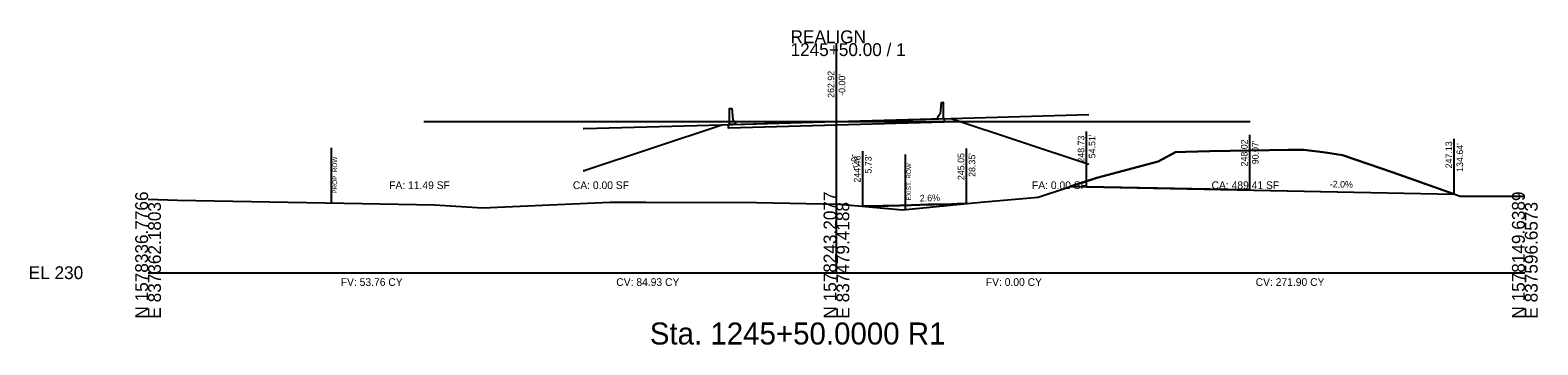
# Model space of a CAD drawing. Extents: x -26 to 6303, y -16 to 9563.
# Drawn here: x 1974.3 to 2302.8, y 6984.3 to 7052.8 of the extents above; entities that cross this region are included whole.
import ezdxf

# ---------------------------------------------------------------- set-up
doc = ezdxf.new("R2010")
doc.units = 0
for name, color, linetype in [('CONST_LV3', 7, 'Continuous'), ('Draft_XS_Grid', 7, 'Continuous'), ('Draft_XS_Text', 7, 'Continuous'), ('DTM_P_FINISHED_GRADE2', 7, 'Continuous'), ('DTM_TEMP_DROP', 7, 'Continuous'), ('DTM_X_GROUND', 7, 'Continuous'), ('TRANS_EOP_PAVED', 7, 'Continuous'), ('XS_CELL', 7, 'Continuous'), ('XS_M_SHAPES_EARTHWORK', 7, 'Continuous'), ('XS_P_ASPHALT', 7, 'Continuous'), ('XS_P_CONCRETE', 7, 'Continuous'), ('XS_P_GROUND', 7, 'Continuous'), ('XS_P_ROW', 7, 'Continuous'), ('XS_P_TX_CLEARZONE', 7, 'Continuous'), ('XS_P_TX_FS_BS', 7, 'Continuous'), ('XS_SHEET_EW_TX_AREA', 7, 'Continuous'), ('XS_SHEET_EW_TX_VOLUME', 7, 'Continuous'), ('XS_X_ROW', 7, 'Continuous')]:
    doc.layers.add(name, color=color, linetype=linetype)

msp = doc.modelspace()

# ---------------------------------------------------------------- linework, layer by layer
at = {"layer": 'CONST_LV3'}
for points in [[(2094.83, 7031.4), (2094.89, 7031.4), (2094.93, 7031.39), (2094.99, 7031.38), (2094.99, 7031.38), (2095, 7031.38), (2095, 7031.38), (2095, 7031.38), (2095, 7031.38), (2095.05, 7031.38), (2125, 7032.22), (2149.96, 7032.92), (2150, 7032.92), (2150, 7032.92), (2175, 7033.62), (2175, 7033.62), (2205, 7034.46)], [(2060.06, 7032.92), (2150.01, 7032.92), (2240.06, 7032.92), (2240.06, 7032.92), (2240.06, 7032.92)], [(2094.83, 7022.24), (2094.89, 7022.24), (2094.93, 7022.23), (2094.99, 7022.22), (2094.99, 7022.22), (2095, 7022.22), (2095, 7022.22), (2095, 7022.22), (2095, 7022.22), (2095.05, 7022.23), (2125, 7032.22), (2149.96, 7032.92), (2150, 7032.92), (2150, 7032.92), (2175, 7033.62), (2175, 7033.62), (2205, 7023.62)]]:
    msp.add_lwpolyline(points, dxfattribs=at)
at = {"layer": 'DTM_P_FINISHED_GRADE2'}
msp.add_lwpolyline([(2155.73, 7014.46), (2156.31, 7014.47), (2156.32, 7014.48), (2156.33, 7014.48), (2160.11, 7014.57), (2160.28, 7014.58), (2161.53, 7014.61), (2166.31, 7014.73), (2169.91, 7014.83), (2170.06, 7014.83), (2171.26, 7014.86), (2171.31, 7014.86), (2175, 7014.96), (2175.06, 7014.96), (2176.29, 7014.99), (2176.31, 7014.99), (2178.35, 7015.05)], dxfattribs=at)
at = {"layer": 'DTM_X_GROUND'}
msp.add_lwpolyline([(2000, 7016), (2006.4, 7015.79), (2046.66, 7015.1), (2062.44, 7014.77), (2072.86, 7014.16), (2100.71, 7015.34), (2108.48, 7015.37), (2132.61, 7015.33), (2150.67, 7014.92), (2164.43, 7013.67), (2181.43, 7015.35), (2193.97, 7016.46), (2206.72, 7020.66), (2220.1, 7024.25), (2223.85, 7026.23), (2226.12, 7026.34), (2231.37, 7026.5), (2240.19, 7026.61), (2248.41, 7026.74), (2251.87, 7026.8), (2256.54, 7026.18), (2260.3, 7025.61), (2271.31, 7021.81), (2285.94, 7016.67), (2300, 7016.69)], dxfattribs=at)
at = {"layer": 'XS_CELL'}
for p, q in [((2150, 7000), (2150, 7050)), ((2000, 7000), (2150, 7000)), ((2150, 7000), (2300, 7000))]:
    msp.add_line(p, q, dxfattribs=at)
at = {"layer": 'XS_M_SHAPES_EARTHWORK'}
msp.add_lwpolyline([(2155.73, 7014.46), (2164.43, 7013.67), (2178.35, 7015.05), (2176.31, 7014.99), (2175.06, 7014.96), (2171.31, 7014.86), (2170.06, 7014.83), (2166.31, 7014.73), (2161.31, 7014.6), (2160.06, 7014.57), (2156.31, 7014.47)], close=True, dxfattribs=at)
at = {"layer": 'XS_P_CONCRETE'}
for points in [[(2126.67, 7032.26), (2126.67, 7035.76), (2127.17, 7035.8), (2127.42, 7033.38), (2128, 7032.55), (2128, 7032.3), (2126.67, 7032.26)], [(2173.33, 7033.57), (2173.33, 7037.07), (2172.83, 7037.03), (2172.58, 7034.62), (2172, 7033.78), (2172, 7033.53), (2173.33, 7033.57)], [(2150, 7032.92), (2173.33, 7033.57), (2173.5, 7033.57), (2173.5, 7032.82), (2150, 7032.17), (2126.5, 7031.51), (2126.5, 7032.26), (2126.67, 7032.26), (2150, 7032.92)]]:
    msp.add_lwpolyline(points, dxfattribs=at)
at = {"layer": 'XS_P_GROUND'}
for points in [[(2239.07, 7018.04), (2204.51, 7018.73)], [(2240.07, 7018.02), (2239.07, 7018.04)], [(2240.07, 7018.02), (2241.07, 7018)], [(2241.07, 7018), (2284.64, 7017.13)], [(2155.73, 7014.46), (2156.31, 7014.47), (2160.06, 7014.57), (2161.31, 7014.6), (2166.31, 7014.73), (2170.06, 7014.83), (2171.31, 7014.86), (2175.06, 7014.96), (2176.31, 7014.99), (2178.35, 7015.05)]]:
    msp.add_lwpolyline(points, dxfattribs=at)
at = {"layer": 'XS_P_ROW'}
msp.add_line((2040, 7015.22), (2040, 7027.22), dxfattribs=at)
at = {"layer": 'XS_P_TX_CLEARZONE'}
for p, q in [((2150, 7032.92), (2150, 7044.92)), ((2204.51, 7018.73), (2204.51, 7030.73)), ((2240.07, 7018.02), (2240.07, 7030.02)), ((2284.64, 7017.13), (2284.64, 7029.13)), ((2155.73, 7014.46), (2155.73, 7026.46)), ((2178.35, 7015.05), (2178.35, 7027.05))]:
    msp.add_line(p, q, dxfattribs=at)
at = {"layer": 'XS_P_TX_FS_BS'}
msp.add_line((2200.93, 7018.79), (2284.64, 7017.13), dxfattribs=at)
msp.add_lwpolyline([(2284.64, 7017.13), (2271.31, 7021.81), (2260.3, 7025.61), (2256.54, 7026.18), (2251.87, 7026.8), (2248.41, 7026.74), (2240.19, 7026.61), (2231.37, 7026.5), (2226.12, 7026.34), (2223.85, 7026.23), (2220.1, 7024.25), (2206.72, 7020.66), (2200.93, 7018.79)], dxfattribs=at)
at = {"layer": 'XS_X_ROW'}
msp.add_line((2165.07, 7013.73), (2165.07, 7025.73), dxfattribs=at)

# ---------------------------------------------------------------- texts
at = {"layer": 'Draft_XS_Grid'}
msp.add_text('-', height=0.0001, dxfattribs=at).set_placement((2000, 7000))
at = {"layer": 'Draft_XS_Text'}
msp.add_text('Sta. 1245+50.0000 R1', height=4.8, dxfattribs=at).set_placement((2109.33, 6984.35))
at = {"layer": 'DTM_TEMP_DROP'}
msp.add_text('X', height=0.24, dxfattribs=at).set_placement((2149.92, 7032.8))
at = {"layer": 'TRANS_EOP_PAVED'}
for p in [(2239.99, 7017.9), (2155.65, 7014.34), (2178.28, 7014.93)]:
    msp.add_text('X', height=0.24, dxfattribs=at).set_placement(p)
at = {"layer": 'XS_CELL'}
for s, p in [('REALIGN', (2140, 7050)), ('1245+50.00 / 1', (2140, 7047.2)), ('EL 230', (1974, 6998.6))]:
    msp.add_text(s, height=2.8, dxfattribs=at).set_placement(p)
for s, p in [('N 1578336.7766', (2000, 6990)), ('N 1578243.2077', (2150, 6990)), ('N 1578149.6389', (2300, 6990)), ('E 837362.1803', (2002.8, 6990)), ('E 837479.4188', (2152.8, 6990)), ('E 837596.6573', (2302.8, 6990))]:
    msp.add_text(s, height=2.8, rotation=90, dxfattribs=at).set_placement(p)
at = {"layer": 'XS_P_ASPHALT'}
for p in [(2204.43, 7018.61), (2284.56, 7017.01)]:
    msp.add_text('X', height=0.24, dxfattribs=at).set_placement(p)
at = {"layer": 'XS_P_ROW'}
msp.add_text('PROP. ROW', height=1, rotation=90, dxfattribs=at).set_placement((2041.2, 7017.22))
at = {"layer": 'XS_P_TX_CLEARZONE'}
for s, p in [('262.92', (2149.52, 7038.09)), ("-0.00'", (2151.92, 7038.53)), ('248.73', (2204.03, 7023.98)), ("54.51'", (2206.43, 7024.93)), ('248.02', (2239.59, 7023.15)), ("90.07'", (2241.99, 7023.63)), ('247.13', (2284.16, 7022.74)), ("134.64'", (2286.56, 7021.97)), ('244.46', (2155.25, 7019.63)), ("5.73'", (2157.65, 7021.59)), ('245.05', (2177.87, 7020.18)), ("28.35'", (2180.27, 7020.88))]:
    msp.add_text(s, height=1.44, rotation=90, dxfattribs=at).set_placement(p)
at = {"layer": 'XS_P_TX_FS_BS'}
for s, rotation, p in [('-0:1', 287.2361, (2152.88, 7025.65)), ('-2.0%', 358.8542, (2257.49, 7018.59)), ('2.6%', 1.4824, (2168.19, 7015.5))]:
    msp.add_text(s, height=1.44, rotation=rotation, dxfattribs=at).set_placement(p)
at = {"layer": 'XS_SHEET_EW_TX_AREA'}
for s, p in [('FA: 11.49 SF', (2052.53, 7018.22)), ('CA: 0.00 SF', (2092.56, 7018.22)), ('FA: 0.00 SF', (2192.6, 7018.22)), ('CA: 489.41 SF', (2231.74, 7018.22))]:
    msp.add_text(s, height=1.68, dxfattribs=at).set_placement(p)
at = {"layer": 'XS_SHEET_EW_TX_VOLUME'}
for s, p in [('FV: 53.76 CY', (2041.99, 6997.12)), ('CV: 84.93 CY', (2102.03, 6997.12)), ('FV: 0.00 CY', (2182.55, 6997.12)), ('CV: 271.90 CY', (2241.35, 6997.12))]:
    msp.add_text(s, height=1.68, dxfattribs=at).set_placement(p)
at = {"layer": 'XS_X_ROW'}
msp.add_text('EXIST. ROW', height=1, rotation=90, dxfattribs=at).set_placement((2166.27, 7015.73))

doc.saveas('drawing.dxf')
